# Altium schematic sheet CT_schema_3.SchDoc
size 401 x 269 mm
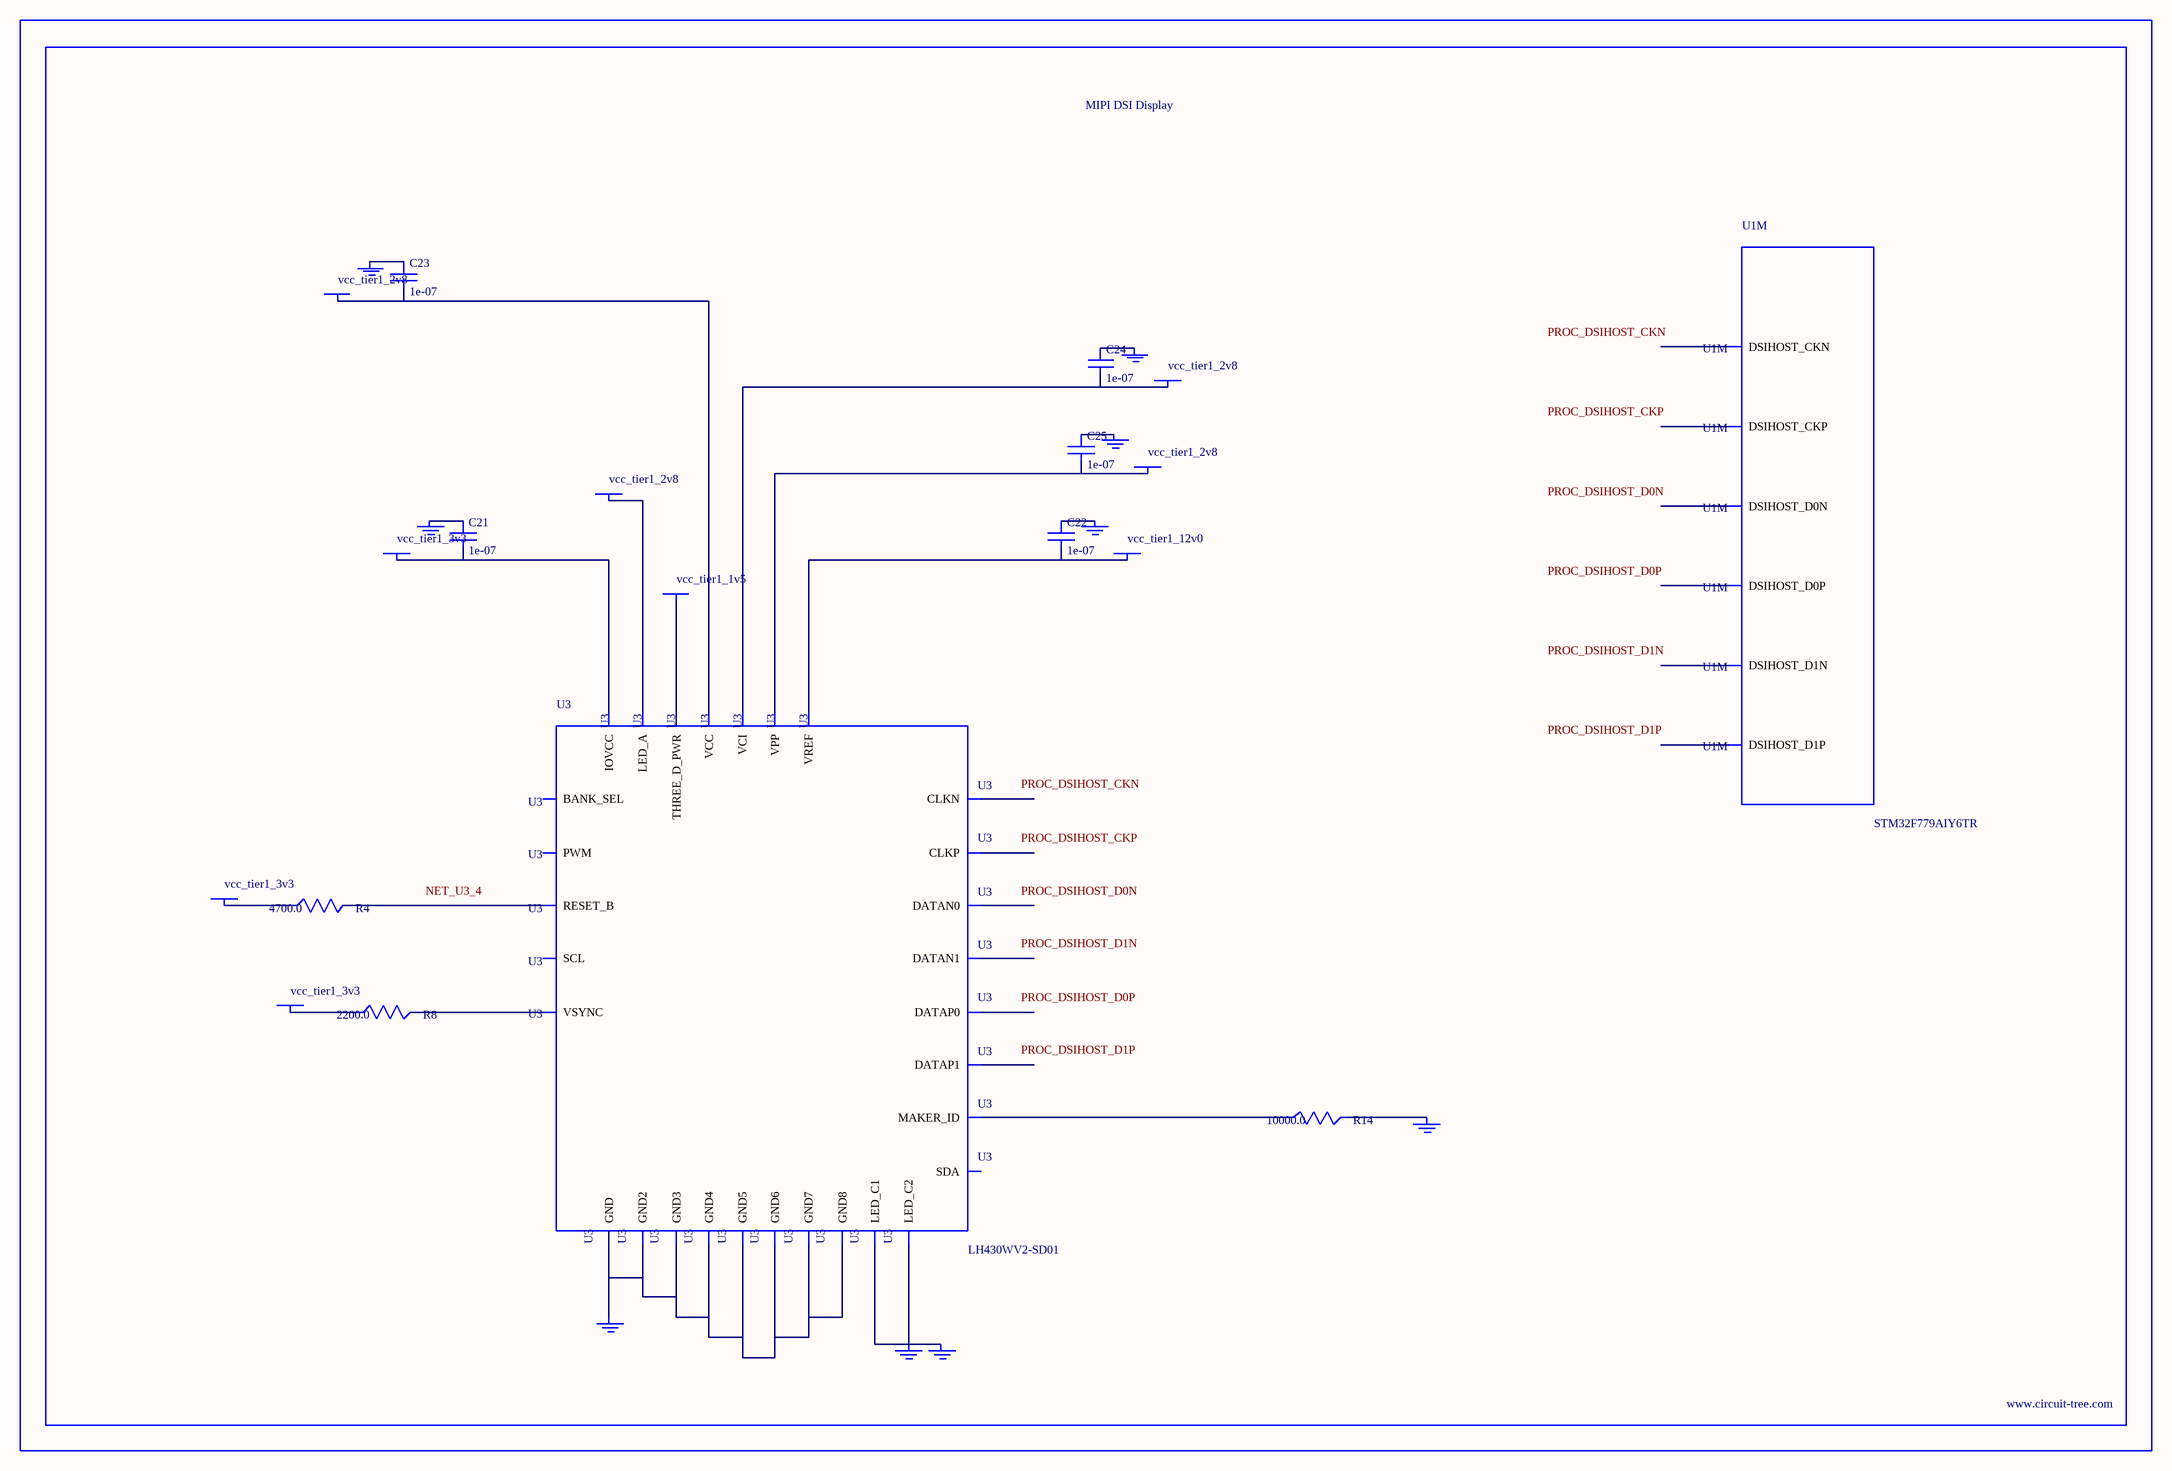
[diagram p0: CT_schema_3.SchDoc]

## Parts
BORDER2  (no value)
C21  1e-07  [C0402]
C22  1e-07  [C0402]
C23  1e-07  [C0402]
C24  1e-07  [C0402]
C25  1e-07  [C0402]
GND_INSTANCE_2_0  (no value)
GND_INSTANCE_2_1  (no value)
GND_INSTANCE_2_2  (no value)
GND_INSTANCE_2_3  (no value)
GND_INSTANCE_2_4  (no value)
GND_INSTANCE_2_5  (no value)
GND_INSTANCE_2_6  (no value)
GND_INSTANCE_2_7  (no value)
GND_INSTANCE_2_8  (no value)
POWER_INSTANCE_2_0  vcc_tier1_3v3
POWER_INSTANCE_2_1  vcc_tier1_2v8
POWER_INSTANCE_2_2  vcc_tier1_2v8
POWER_INSTANCE_2_3  vcc_tier1_2v8
POWER_INSTANCE_2_4  vcc_tier1_2v8
POWER_INSTANCE_2_5  vcc_tier1_12v0
POWER_INSTANCE_2_6  vcc_tier1_3v3
POWER_INSTANCE_2_7  vcc_tier1_3v3
POWER_INSTANCE_2_8  vcc_tier1_1v5
R4  4700.0  [R0603]
R8  2200.0  [R0603]
R14  10000.0  [R0603]
U1  STM32F779AIY6TR  [WLCSP180]  (part M of 15)
U3  LH430WV2-SD01  [LH430WV2-SD01]

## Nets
NetC21_1: C21.1 GND_INSTANCE_2_0.0(GND)
NetC21_2: C21.2 POWER_INSTANCE_2_0.0(PWR) U3.2(IOVCC)
NetC22_1: C22.1 GND_INSTANCE_2_7.0(GND)
NetC22_2: C22.2 POWER_INSTANCE_2_5.0(PWR) U3.30(VREF)
NetC23_1: C23.1 GND_INSTANCE_2_5.0(GND)
NetC23_2: C23.2 POWER_INSTANCE_2_3.0(PWR) U3.22(VCC)
NetC24_1: C24.1 GND_INSTANCE_2_4.0(GND)
NetC24_2: C24.2 POWER_INSTANCE_2_2.0(PWR) U3.21(VCI)
NetC25_1: C25.1 GND_INSTANCE_2_6.0(GND)
NetC25_2: C25.2 POWER_INSTANCE_2_4.0(PWR) U3.23(VPP)
NetGND_INSTANCE_2_1_0: GND_INSTANCE_2_1.0(GND) GND_INSTANCE_2_2.0(GND) U3.17(LED_C1) U3.18(LED_C2)
NetGND_INSTANCE_2_3_0: GND_INSTANCE_2_3.0(GND) R14.2
NetGND_INSTANCE_2_8_0: GND_INSTANCE_2_8.0(GND) U3.1(GND) U3.6(GND2) U3.9(GND3) U3.12(GND4) U3.15(GND5) U3.19(GND6) U3.24(GND7) U3.27(GND8)
NetPOWER_INSTANCE_2_1_0: POWER_INSTANCE_2_1.0(PWR) U3.16(LED_A)
NetPOWER_INSTANCE_2_6_0: POWER_INSTANCE_2_6.0(PWR) R4.1
NetPOWER_INSTANCE_2_7_0: POWER_INSTANCE_2_7.0(PWR) R8.1
NetPOWER_INSTANCE_2_8_0: POWER_INSTANCE_2_8.0(PWR) U3.29(THREE_D_PWR)
NetR4_2: R4.2 U3.4(RESET_B)
NetR8_2: R8.2 U3.5(VSYNC)
NetR14_1: R14.1 U3.20(MAKER_ID)

Not connected (* = marked no-connect by the designer): U1 H1(DSIHOST_D1P) H2(DSIHOST_D1N) H3(DSIHOST_CKN) H4(DSIHOST_CKP) J1(DSIHOST_D0P) J2(DSIHOST_D0N); U3 3(PWM) 7(DATAN0) 8(DATAP0) 10(DATAN1) 11(DATAP1) 13(CLKN) 14(CLKP) 25(SCL) 26(SDA) 28(BANK_SEL)

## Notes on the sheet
- Labels drawn without touching a wire or pin: NET_U3_4, PROC_DSIHOST_CKN, PROC_DSIHOST_CKP, PROC_DSIHOST_D0N, PROC_DSIHOST_D0P, PROC_DSIHOST_D1N, PROC_DSIHOST_D1P

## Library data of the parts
BORDER2 = BORDER_PAGE2
C21-C25 = C0402C104K3RACTU
GND_INSTANCE_2_0-GND_INSTANCE_2_8 = GND
POWER_INSTANCE_2_0-POWER_INSTANCE_2_8 = PWR
R4 = RC0603JR-074K7L
R8 = RC0603JR-072K2L
R14 = RC0603JR-0710KL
